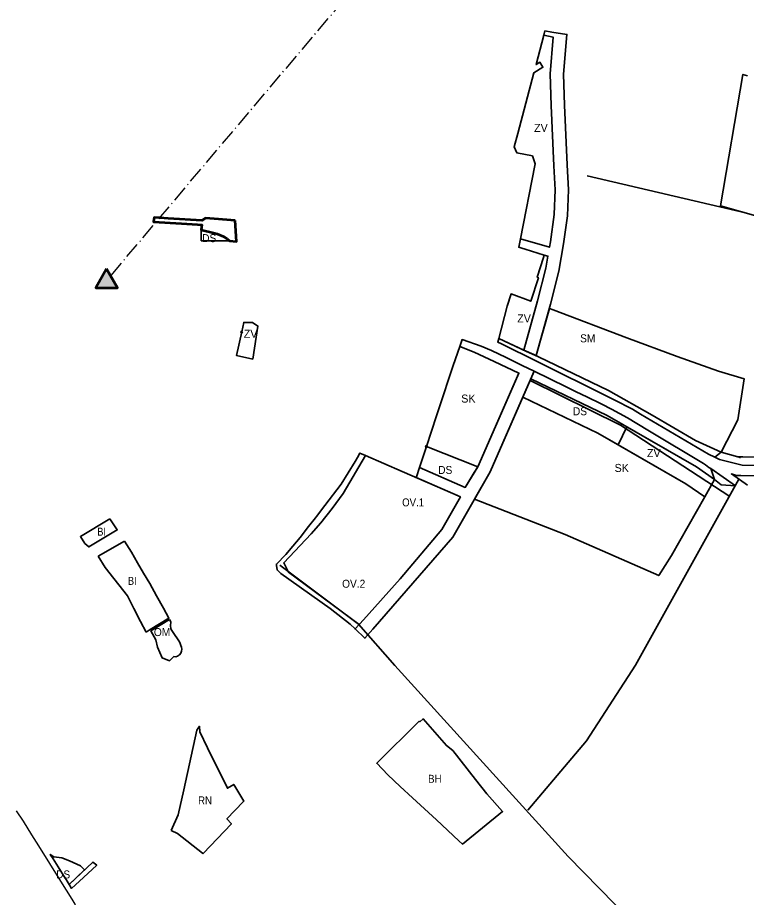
# Model space of a CAD drawing. Extents: x -650276 to -642489, y -1074311 to -1066720.
# Drawn here: x -646730 to -645637, y -1072023 to -1070703 of the extents above; entities that cross this region are included whole.
import ezdxf

# ---------------------------------------------------------------- set-up
doc = ezdxf.new("R2010")
doc.units = 0
doc.header["$LTSCALE"] = 4.8
doc.header["$PDMODE"] = 32
doc.header["$PDSIZE"] = 2.4
doc.linetypes.add('DOT_DASHED', pattern=[7.7, 5, -1.2, 0.3, -1.2])
for name, color, linetype, lineweight in [('1', 7, 'Continuous', 35), ('11', 7, 'Continuous', 35), ('12', 7, 'Continuous', 35), ('15', 7, 'Continuous', 35), ('18', 7, 'Continuous', 35), ('2', 7, 'Continuous', 35), ('20', 7, 'Continuous', 35), ('24', 7, 'Continuous', 35), ('40', 7, 'Continuous', 35), ('46', 7, 'Continuous', 35), ('54', 7, 'Continuous', 35), ('55', 7, 'Continuous', 53), ('60', 7, 'Continuous', 53), ('61', 7, 'Continuous', 25), ('7', 7, 'Continuous', 35)]:
    doc.layers.add(name, color=color, linetype=linetype, lineweight=lineweight)
doc.layers.add('62', color=7, linetype='Continuous')

msp = doc.modelspace()

# ---------------------------------------------------------------- hatches: boundary and pattern name
at = {"layer": '55'}
msp.add_hatch(color=256, dxfattribs=at).paths.add_polyline_path([(-646596.857, -1071079.969), (-646612.808, -1071108.615), (-646580.424, -1071108.615)])

# ---------------------------------------------------------------- linework, layer by layer
at = {"layer": '1'}
msp.add_lwpolyline([(-646102.04, -1071906.4), (-646068.317, -1071937.555), (-646062.91, -1071942.55), (-646002.93, -1071893.984), (-646026.64, -1071867.44), (-646043.49, -1071845.87), (-646077.32, -1071802.59), (-646087, -1071795), (-646104.5, -1071774.86), (-646122.16, -1071754.78), (-646127.12, -1071759.15), (-646127.84, -1071758.53), (-646191.57, -1071821.44), (-646174.69, -1071838.69), (-646156.59, -1071856.53), (-646137.74, -1071873.31)], close=True, dxfattribs=at)
at = {"layer": '11'}
msp.add_lwpolyline([(-646066.165, -1071422.155), (-646153.5, -1071383.85), (-646208.577, -1071360.044), (-646241.68, -1071416.887), (-646258.487, -1071439.265), (-646275.615, -1071460.886), (-646289.976, -1071477.514), (-646330.914, -1071521.11), (-646324, -1071535), (-646217.978, -1071613.552), (-646211.407, -1071606.247), (-646156.471, -1071545.166), (-646094.063, -1071471.007)], close=True, dxfattribs=at)
at = {"layer": '12'}
msp.add_lwpolyline([(-646502.39, -1071605.72), (-646530.27, -1071622.79), (-646522.99, -1071636.22), (-646520.32, -1071647.59), (-646513.43, -1071663.64), (-646502.53, -1071667.82), (-646496.06, -1071661.5), (-646492.89, -1071661.75), (-646490.07, -1071660.88), (-646487.36, -1071659.1), (-646485.29, -1071656.53), (-646484.15, -1071653.38), (-646483.97, -1071650.63), (-646484.38, -1071647.41), (-646485.2, -1071644.85), (-646486.31, -1071641.97), (-646487.56, -1071639.23), (-646497.83, -1071624.02), (-646499.829, -1071620.704), (-646500.289, -1071619.291), (-646500.83, -1071615.62), (-646500.34, -1071609.66)], close=True, dxfattribs=at)
at = {"layer": '15'}
for points in [[(-645911.345, -1070788.463), (-645906.373, -1070728.716), (-645929.077, -1070725.068), (-645939.27, -1070723.43), (-645940.955, -1070729.799), (-645926.784, -1070732.812), (-645931.369, -1070787.913), (-645930.036, -1070835.367), (-645926.084, -1070925.481), (-645923.919, -1070961.855), (-645925.626, -1070998.754), (-645931.24, -1071039.686), (-645932.635, -1071047.688), (-645976.17, -1071035.39), (-645978.58, -1071047.68), (-645973.77, -1071049.17), (-645968.97, -1071050.66), (-645940.25, -1071059.59), (-645934.978, -1071061.119), (-645938.15, -1071079.311), (-645950.283, -1071128.057), (-645970.966, -1071202.169), (-645952.419, -1071210.117), (-645930.943, -1071133.161), (-645918.57, -1071083.449), (-645911.474, -1071042.764), (-645905.69, -1071000.578), (-645903.891, -1070961.723), (-645906.11, -1070924.449), (-645910.048, -1070834.649)], [(-645694.15, -1071357.83), (-645684.785, -1071362.539), (-645674.947, -1071355.071), (-645713.428, -1071337.765), (-645778.69, -1071299.362), (-645844.079, -1071262.487), (-645948.761, -1071211.885), (-645967, -1071204), (-646008.714, -1071184.746), (-646010.14, -1071190.08), (-646004.65, -1071192.55), (-645951.118, -1071219.11), (-645843.45, -1071272.53), (-645835.76, -1071276.35), (-645808.13, -1071290.78), (-645795.97, -1071297.93), (-645694.15, -1071357.83)], [(-646094.063, -1071471.007), (-646156.471, -1071545.166), (-646211.407, -1071606.247), (-646223.928, -1071620.168), (-646209.322, -1071634.004), (-646197.398, -1071620.579), (-646077.593, -1071482.499), (-646021.674, -1071384.575), (-645964.396, -1071254.314), (-645955.342, -1071233.725), (-645973.324, -1071224.925), (-645989.7, -1071216.91), (-645997.62, -1071213.03), (-646019.41, -1071202.36), (-646035.06, -1071195.87), (-646063.59, -1071186.33), (-646067.097, -1071196.699), (-646045.462, -1071204.917), (-646015.387, -1071218.854), (-645978.403, -1071236.481), (-646040.084, -1071376.813), (-646058.719, -1071407.796), (-646127.301, -1071378.036), (-646131.79, -1071391.83), (-646132.229, -1071393.179), (-646066.165, -1071422.155)], [(-646275.615, -1071460.886), (-646258.487, -1071439.265), (-646241.68, -1071416.887), (-646208.577, -1071360.044), (-646217.049, -1071356.382), (-646220.61, -1071363.16), (-646223.77, -1071369.24), (-646245.1, -1071403.04), (-646269.2, -1071435.22), (-646281.99, -1071451.4), (-646283.52, -1071453.34), (-646293.87, -1071466.43), (-646306.14, -1071482.86), (-646317.52, -1071496.12), (-646327.97, -1071508.29), (-646341.88, -1071522.81), (-646341.66, -1071524.87), (-646340.93, -1071531.64), (-646335.3, -1071537.05), (-646261.46, -1071589.38), (-646231.43, -1071613.06), (-646223.928, -1071620.168), (-646217.978, -1071613.552), (-646324, -1071535), (-646330.914, -1071521.11), (-646289.976, -1071477.514), (-646275.615, -1071460.886)], [(-646652.864, -1072003.075), (-646617.21, -1071969.689), (-646611.438, -1071974.36), (-646631.409, -1071992.798), (-646649.112, -1072009.049)]]:
    msp.add_lwpolyline(points, close=True, dxfattribs=at)
for points in [[(-645701.44, -1071372.25), (-645782.32, -1071323.5), (-645784.92, -1071321.93), (-645815.65, -1071303.41), (-645839.37, -1071290.6), (-645854.1, -1071282.93), (-645856.26, -1071281.91), (-645875.48, -1071272.81), (-645893.41, -1071264.04), (-645907.62, -1071257.08), (-645955.342, -1071233.725), (-645960.34, -1071245.09), (-645846, -1071300), (-645712, -1071377), (-645712, -1071377)], [(-645712, -1071377), (-645685.098, -1071395.824), (-645690.677, -1071379.721)]]:
    msp.add_lwpolyline(points, dxfattribs=at)
msp.add_arc((-645538.107, -1071148.434), 277.076, 233.87926, 236.5888, dxfattribs=at)
at = {"layer": '18'}
for points in [[(-645926.81, -1071141.595), (-645932.502, -1071139.426), (-645952.419, -1071210.117), (-645948.761, -1071211.885)], [(-645678.86, -1071233.58), (-645741.09, -1071211.36), (-645816.47, -1071183.63), (-645926.81, -1071141.595)], [(-645948.761, -1071211.885), (-645844.079, -1071262.487), (-645778.69, -1071299.362), (-645713.428, -1071337.765), (-645674.947, -1071355.071)], [(-645674.947, -1071355.071), (-645650.09, -1071306.433), (-645640.737, -1071244.963), (-645678.86, -1071233.58)]]:
    msp.add_lwpolyline(points, dxfattribs=at)
at = {"layer": '2'}
msp.add_line((-646609.21, -1071510.98), (-646570, -1071488.38), dxfattribs=at)
msp.add_lwpolyline([(-646591.65, -1071454.91), (-646635.79, -1071481.6), (-646629.37, -1071491.74), (-646623.18, -1071496.99), (-646580.58, -1071471.48)], close=True, dxfattribs=at)
for points in [[(-646570, -1071488.38), (-646559.53, -1071505.12), (-646550.23, -1071520.88), (-646541.14, -1071536.3), (-646532.04, -1071551.72), (-646521.8, -1071570.34), (-646511.47, -1071589.11), (-646503.31, -1071603.95), (-646531.2, -1071621.07), (-646537.28, -1071624.8)], [(-646537.28, -1071624.8), (-646545.89, -1071609.07), (-646555.78, -1071589.66), (-646565.17, -1071570.4), (-646598.63, -1071527.8), (-646609.21, -1071510.98)]]:
    msp.add_lwpolyline(points, dxfattribs=at)
at = {"layer": '20'}
for points in [[(-645990.48, -1071263.958), (-645978.403, -1071236.481), (-646015.387, -1071218.854), (-646045.462, -1071204.917), (-646067.097, -1071196.699), (-646076.713, -1071225.138)], [(-646076.713, -1071225.138), (-646098.66, -1071290.03), (-646102.011, -1071300.326), (-646117.031, -1071346.48)], [(-646117.031, -1071346.48), (-646040.084, -1071376.813), (-645990.48, -1071263.958)]]:
    msp.add_lwpolyline(points, dxfattribs=at)
msp.add_lwpolyline([(-645699.825, -1071422.134), (-645728.105, -1071402.346), (-645859.986, -1071326.563), (-645972.422, -1071272.568), (-646021.674, -1071384.575), (-646044.948, -1071425.333), (-645909.13, -1071478.56), (-645768.62, -1071540.17), (-645749.631, -1071509.908)], close=True, dxfattribs=at)
msp.add_point((-646117.031, -1071346.48), dxfattribs=at)
at = {"layer": '24'}
for points in [[(-646454.59, -1071021.54), (-646454.59, -1071038), (-646412.54, -1071038.01), (-646415.61, -1071035.4), (-646421.58, -1071031.81), (-646430.91, -1071027.44)], [(-645829.706, -1071343.963), (-645816.714, -1071316.828), (-645846, -1071300), (-645960.34, -1071245.09), (-645972.422, -1071272.568), (-645859.986, -1071326.563)], [(-646045.393, -1071385.64), (-646040.084, -1071376.813), (-646117.031, -1071346.48), (-646127.301, -1071378.036), (-646058.719, -1071407.796)], [(-645675.177, -1071403.922), (-645675.177, -1071403.922), (-645653.742, -1071405.36), (-645690.677, -1071379.721), (-645685.098, -1071395.824)], [(-646652.18, -1071967.73), (-646636.01, -1071975.35), (-646629.655, -1071981.343), (-646652.864, -1072003.075), (-646657.32, -1071995.98), (-646658.79, -1071993.62), (-646669.31, -1071976.77), (-646676.79, -1071964.97), (-646681.07, -1071958.16), (-646675.99, -1071961.64), (-646663.87, -1071963.26)]]:
    msp.add_lwpolyline(points, close=True, dxfattribs=at)
for points in [[(-645539.738, -1071364.092), (-645642.431, -1071362.259), (-645650.28, -1071362.07), (-645674.947, -1071355.071), (-645684.785, -1071362.539), (-645677.58, -1071366.16), (-645643.56, -1071374.75), (-645497.84, -1071377.53)], [(-645558.9, -1071391.8), (-645645.368, -1071389.96), (-645651.93, -1071389.82), (-645659.6, -1071387.71), (-645647.727, -1071396.036), (-645635.795, -1071404.403)]]:
    msp.add_lwpolyline(points, dxfattribs=at)
at = {"layer": '40'}
for points in [[(-645932.635, -1071047.688), (-645931.24, -1071039.686), (-645925.626, -1070998.754), (-645923.919, -1070961.855), (-645926.084, -1070925.481), (-645930.036, -1070835.367), (-645931.369, -1070787.913), (-645926.784, -1070732.812), (-645940.955, -1070729.799), (-645952.65, -1070773.98), (-645946.81, -1070770.47), (-645942.3, -1070777.96), (-645955.86, -1070786.21), (-645980.01, -1070877.28), (-645985.28, -1070897.13), (-645981.48, -1070906.35), (-645958.21, -1070910.84), (-645954.01, -1070922.8), (-645954.492, -1070925.251), (-645976.17, -1071035.39)], [(-645970.966, -1071202.169), (-645950.283, -1071128.057), (-645938.15, -1071079.311), (-645934.978, -1071061.119), (-645940.25, -1071059.59), (-645941.45, -1071063.3), (-645950.96, -1071092.8), (-645949.21, -1071093.62), (-645960.66, -1071128.71), (-645990.14, -1071117.76), (-645995.74, -1071136.22), (-646008.714, -1071184.746)], [(-645712, -1071377), (-645816.714, -1071316.828), (-645829.706, -1071343.963), (-645728.105, -1071402.346), (-645699.825, -1071422.134), (-645685.098, -1071395.824)]]:
    msp.add_lwpolyline(points, close=True, dxfattribs=at)
for points in [[(-646377.5, -1071215.56), (-646369.76, -1071166.06), (-646377.87, -1071160.66), (-646391.07, -1071160.52), (-646394.05, -1071174.83)], [(-646394.05, -1071174.83), (-646401.64, -1071210.18), (-646377.5, -1071215.56)]]:
    msp.add_lwpolyline(points, dxfattribs=at)
msp.add_point((-646394.05, -1071174.83), dxfattribs=at)
at = {"layer": '46'}
msp.add_lwpolyline([(-645635.482, -1070790.628), (-645642.52, -1070788.7), (-645676.292, -1070985.89), (-645615.899, -1071002.753)], dxfattribs=at)
at = {"layer": '54'}
for p, q in [((-645875.986, -1070940.86), (-645638.682, -1070996.266)), ((-645650.559, -1071361.544), (-645646.066, -1071363.608))]:
    msp.add_line(p, q, dxfattribs=at)
for points in [[(-645961.323, -1071247.326), (-645825.908, -1071314.509), (-645661.944, -1071421.517)], [(-645648.577, -1071395.44), (-645803.784, -1071674.386), (-645877, -1071788), (-645965, -1071892)], [(-646336.784, -1071524.232), (-646218.737, -1071612.767), (-646164.374, -1071674.897), (-645904.456, -1071961.331), (-645718.199, -1072151.712), (-645526.944, -1072343.922), (-645538, -1072384), (-645459, -1072440), (-645389, -1072483), (-645335, -1072526), (-645287, -1072569), (-645227, -1072617), (-645139.573, -1072694.628), (-645084.365, -1072788.086)]]:
    msp.add_lwpolyline(points, dxfattribs=at)
at = {"layer": '55', "linetype": 'DOT_DASHED', "lineweight": 25}
msp.add_line((-646590, -1071090), (-645744.292, -1070089.84), dxfattribs=at)
at = {"layer": '55'}
msp.add_lwpolyline([(-646596.857, -1071079.969), (-646612.808, -1071108.615), (-646580.424, -1071108.615)], close=True, dxfattribs=at)
at = {"layer": '60'}
msp.add_lwpolyline([(-646403.81, -1071007.7), (-646435.28, -1071005.2), (-646448.48, -1071004.25), (-646453.7, -1071007.79), (-646504.25, -1071004.54), (-646516.78, -1071003.78), (-646525.4, -1071003.29), (-646526.31, -1071009.55), (-646484.27, -1071012.11), (-646460.09, -1071013.61), (-646454.02, -1071013.98), (-646454.59, -1071021.54), (-646436.15, -1071025.97), (-646430.91, -1071027.44), (-646421.58, -1071031.81), (-646415.61, -1071035.4), (-646412.54, -1071038.01), (-646402.09, -1071038.95)], close=True, dxfattribs=at)
at = {"layer": '61'}
msp.add_lwpolyline([(-646732.05, -1071892.58), (-646721.96, -1071908.47), (-646709.19, -1071928.91), (-646698.88, -1071945.32), (-646665.78, -1071998.02), (-646648.65, -1072025.26), (-646644.03, -1072032.61), (-646642.27, -1072036.3)], dxfattribs=at)
at = {"layer": '7'}
for points in [[(-646453.04, -1071956.3), (-646451.87, -1071956.88), (-646409.4, -1071912.17), (-646416.2, -1071904.81), (-646391.83, -1071879.32), (-646390.732, -1071878.171), (-646405.99, -1071853.26), (-646415.46, -1071859.05), (-646445.115, -1071798.418), (-646456.96, -1071774.2), (-646457.52, -1071765.98), (-646461.09, -1071771.76), (-646480.81, -1071861.18), (-646489.34, -1071898.61), (-646499.741, -1071922.455)], [(-646499.741, -1071922.455), (-646490.111, -1071926.754), (-646453.04, -1071956.3)]]:
    msp.add_lwpolyline(points, dxfattribs=at)

# ---------------------------------------------------------------- texts
at = {"layer": '62'}
for s, p in [('ZV', (-645955.588, -1070874.768)), ('ZV', (-645980.931, -1071160.591)), ('ZV', (-646390.931, -1071183.591)), ('SK', (-646064.883, -1071280.659)), ('ZV', (-645786.398, -1071362.507)), ('SK', (-645834.883, -1071384.659))]:
    msp.add_text(s, height=12, dxfattribs=at).set_placement(p)
for s, width, p in [('DS', 0.95, (-646453.386, -1071040.148)), ('SM', 0.95, (-645886.606, -1071190.345)), ('DS', 0.95, (-645897.407, -1071299.717)), ('DS', 0.95, (-646099.407, -1071387.717)), ('OV.1', 0.9, (-646153.486, -1071436.306)), ('BI', 0.85, (-646610.515, -1071480.22)), ('BI', 0.85, (-646564.529, -1071553.971)), ('OV.2', 0.95, (-646243.486, -1071558.306)), ('OM', 0.95, (-646525.703, -1071630.756)), ('BH', 0.9, (-646114.48, -1071850.818)), ('RN', 0.9, (-646459.448, -1071883.14)), ('DS', 0.95, (-646672.386, -1071994.148))]:
    msp.add_text(s, height=12, dxfattribs=dict(at, width=width)).set_placement(p)

doc.saveas('drawing.dxf')
